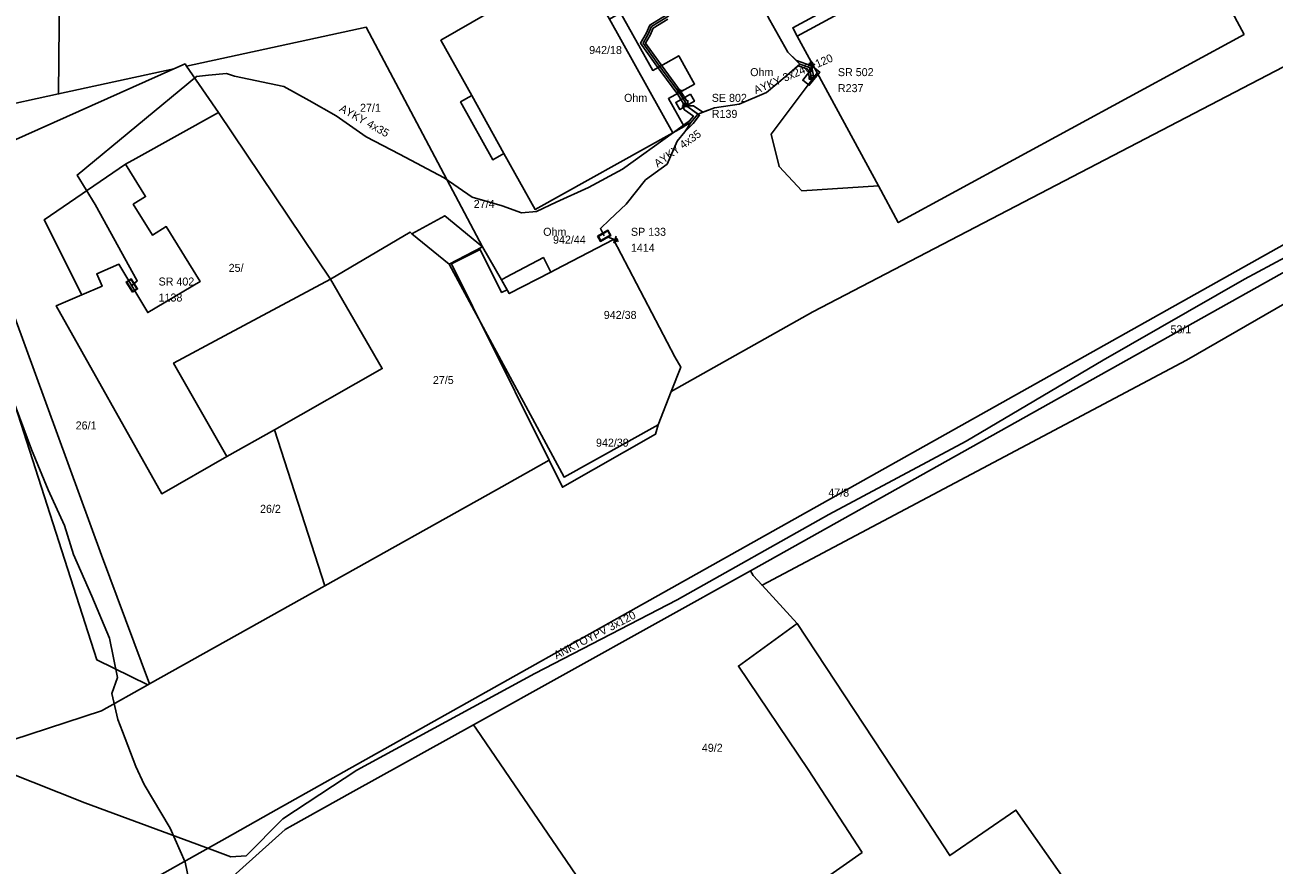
# Model space of a CAD drawing. Extents: x -793400 to -756198, y -1074141 to -1042963.
# Drawn here: x -783184.8 to -783067.8, y -1065311.3 to -1065232.6 of the extents above; entities that cross this region are included whole.
import ezdxf

# ---------------------------------------------------------------- set-up
doc = ezdxf.new("R2010")
doc.units = 0
for name, color, linetype in [('Parcela', 7, 'Continuous'), ('Popiskový text - Parcela', 7, 'Continuous'), ('Popiskový text - Přípojková skříň nn - SJZ', 7, 'Continuous'), ('Popiskový text - Přípojková skříň nn - Typ', 7, 'Continuous'), ('Popiskový text - Rozpojovací skříň nn - SJZ', 7, 'Continuous'), ('Popiskový text - Rozpojovací skříň nn - Typ', 7, 'Continuous'), ('Popiskový text - Uzemnění - Odpor', 7, 'Continuous'), ('Popiskový text - Vedení nn kabelové', 7, 'Continuous'), ('Popiskový text - Vedení vn kabelové', 7, 'Continuous'), ('Skříň', 7, 'Continuous'), ('Spojnice nn', 7, 'Continuous'), ('Spojnice vn', 7, 'Continuous'), ('Stavební objekt', 7, 'Continuous'), ('Uzemnění', 7, 'Continuous'), ('Vedení 22 kV kabelové', 7, 'Continuous'), ('Vedení nn kabelové', 7, 'Continuous')]:
    doc.layers.add(name, color=color, linetype=linetype)

msp = doc.modelspace()

# ---------------------------------------------------------------- linework, layer by layer
at = {"layer": 'Parcela'}
for points in [[(-782802.96, -1065191.56), (-783035.19, -1065351.07), (-783035.53, -1065350.83), (-783038.17, -1065350.24), (-783040.99, -1065346.21), (-783044.07, -1065348.33), (-783047.92, -1065345.19), (-783053.56, -1065344.29), (-783058.74, -1065346.24), (-783070.11, -1065329.81), (-783075.77, -1065329.23), (-783091.97, -1065306.14), (-783098.16, -1065310.4), (-783100.87, -1065306.26), (-783112.47, -1065288.65), (-783115.75, -1065285.08), (-783075.98, -1065264), (-783047.31, -1065247.47), (-783047.3, -1065244.78), (-783016.9, -1065227.41), (-782970.29, -1065201.58), (-782969.82, -1065201.89), (-782969.07, -1065202.37), (-782882.22, -1065152.82)], [(-783169.31, -1065352.34), (-783175.94, -1065340.1), (-783182.62, -1065330.47), (-783184.48, -1065327.78), (-783187.81, -1065328.54), (-783187.72, -1065300.11), (-783177.68, -1065296.84), (-783173.32, -1065294.4), (-783173.16, -1065294.31), (-783156.73, -1065285.12), (-783140.65, -1065276.14), (-783135.72, -1065273.37), (-783134.47, -1065275.89), (-783125.74, -1065270.93), (-783125.51, -1065270.04), (-783124.29, -1065266.93), (-783111, -1065259.46), (-783050.92, -1065228.15), (-783004.72, -1065202.26), (-782983.18, -1065192.04), (-782974.5, -1065189.1), (-782967.33, -1065186.68)], [(-783181.56, -1065226.08), (-783181.69, -1065239.04), (-783194.28, -1065241.77), (-783196.65, -1065233.93), (-783199.83, -1065235.73), (-783237.43, -1065216.95)], [(-783050.92, -1065228.15), (-783111, -1065259.46), (-783124.29, -1065266.93), (-783123.38, -1065264.63), (-783123.94, -1065263.66), (-783129.68, -1065252.69), (-783135.14, -1065255.52), (-783135.55, -1065255.73), (-783136.25, -1065254.38), (-783139.73, -1065256.22), (-783140.19, -1065256.46), (-783141.97, -1065253.35), (-783152.85, -1065232.79), (-783169.7, -1065236.44), (-783169.84, -1065236.23), (-783170.9, -1065236.7), (-783181.69, -1065239.04), (-783181.56, -1065226.08)], [(-783030.13, -1065225.97), (-783047.29, -1065238.34), (-783047.3, -1065242.19), (-783117.31, -1065281.44), (-783154.96, -1065302.57), (-783161.79, -1065306.4), (-783165.39, -1065308.42), (-783174.79, -1065313.7), (-783175.5, -1065314.93), (-783176.75, -1065317.97), (-783176.79, -1065320.46), (-783175.95, -1065323.2), (-783173.92, -1065326.44), (-783170.91, -1065331.24), (-783170.98, -1065331.8), (-783171.31, -1065334.39), (-783166.81, -1065343.66), (-783166.32, -1065344.67), (-783164.64, -1065348.16), (-783161.08, -1065352.99)]]:
    msp.add_lwpolyline(points, dxfattribs=at)
for points in [[(-783237.43, -1065216.95), (-783199.83, -1065235.73), (-783196.65, -1065233.93), (-783194.28, -1065241.77), (-783178.12, -1065292.05), (-783173.32, -1065294.4), (-783177.68, -1065296.84), (-783187.72, -1065300.11), (-783190.56, -1065290.52), (-783205.72, -1065239.34), (-783207.03, -1065237.99), (-783208.59, -1065236.96), (-783235.05, -1065225.06), (-783238.13, -1065225.57), (-783243.03, -1065216.54), (-783256.12, -1065192.4), (-783266.62, -1065172.96), (-783272.44, -1065162), (-783267.78, -1065160.5), (-783264.5, -1065166.6)], [(-783070.56, -1065233.47), (-783079.93, -1065216.01), (-783080.35, -1065215.23), (-783112.88, -1065232.84), (-783112.46, -1065233.62), (-783110.6, -1065237.06), (-783114.9, -1065242.82), (-783114.17, -1065245.85), (-783112.04, -1065248.11), (-783104.86, -1065247.66), (-783103, -1065251.1)], [(-783070.56, -1065233.47), (-783103, -1065251.1), (-783104.86, -1065247.66), (-783112.04, -1065248.11), (-783114.17, -1065245.85), (-783114.9, -1065242.82), (-783110.6, -1065237.06), (-783112.46, -1065233.62), (-783112.88, -1065232.84), (-783080.35, -1065215.23), (-783079.93, -1065216.01)], [(-783133.08, -1065226.62), (-783145.87, -1065234.01), (-783142.97, -1065239.2), (-783144.02, -1065239.79), (-783141, -1065245.2), (-783139.95, -1065244.61), (-783137.01, -1065249.88), (-783124.11, -1065242.68), (-783123.06, -1065242.09), (-783124.53, -1065239.48), (-783122.08, -1065238.11), (-783123.56, -1065235.46), (-783126, -1065236.83), (-783129.01, -1065231.44), (-783130.06, -1065232.03)], [(-783133.08, -1065226.62), (-783130.06, -1065232.03), (-783129.01, -1065231.44), (-783126, -1065236.83), (-783123.56, -1065235.46), (-783122.08, -1065238.11), (-783124.53, -1065239.48), (-783123.06, -1065242.09), (-783124.11, -1065242.68), (-783137.01, -1065249.88), (-783139.95, -1065244.61), (-783141, -1065245.2), (-783144.02, -1065239.79), (-783142.97, -1065239.2), (-783145.87, -1065234.01)], [(-783152.85, -1065232.79), (-783141.97, -1065253.35), (-783145.48, -1065250.45), (-783148.59, -1065252.14), (-783148.74, -1065251.98), (-783156.21, -1065256.38), (-783166.69, -1065240.77), (-783169.7, -1065236.44)], [(-783173.16, -1065294.31), (-783173.32, -1065294.4), (-783178.12, -1065292.05), (-783194.28, -1065241.77), (-783181.69, -1065239.04), (-783170.9, -1065236.7), (-783179.76, -1065240.65), (-783191.05, -1065245.69), (-783177.67, -1065282.27)], [(-783181.91, -1065258.89), (-783172.02, -1065276.5), (-783165.93, -1065273.01), (-783161.45, -1065270.5), (-783156.73, -1065285.12), (-783173.16, -1065294.31), (-783177.67, -1065282.27), (-783191.05, -1065245.69), (-783179.76, -1065240.65), (-783170.9, -1065236.7), (-783169.84, -1065236.23), (-783169.7, -1065236.44), (-783166.69, -1065240.77), (-783174.44, -1065245.09), (-783175.41, -1065245.63), (-783183.05, -1065250.84), (-783179.51, -1065257.86)], [(-783165.93, -1065273.01), (-783172.02, -1065276.5), (-783181.91, -1065258.89), (-783179.51, -1065257.86), (-783183.05, -1065250.84), (-783175.41, -1065245.63), (-783174.44, -1065245.09), (-783166.69, -1065240.77), (-783156.21, -1065256.38), (-783151.35, -1065264.77), (-783161.45, -1065270.5)], [(-783172.94, -1065321.3), (-783175.95, -1065323.2), (-783176.79, -1065320.46), (-783176.75, -1065317.97), (-783175.5, -1065314.93), (-783174.79, -1065313.7), (-783165.39, -1065308.42), (-783161.79, -1065306.4), (-783154.96, -1065302.57), (-783117.31, -1065281.44), (-783047.3, -1065242.19), (-783047.3, -1065244.78), (-783049.56, -1065246.07), (-783116.83, -1065283.73), (-783142.8, -1065298.14), (-783154.07, -1065304.4), (-783160.02, -1065307.71), (-783160.46, -1065307.95), (-783165.63, -1065312.63), (-783167.76, -1065315.47), (-783169.32, -1065319.01)], [(-783075.98, -1065264), (-783115.75, -1065285.08), (-783116.58, -1065284.17), (-783116.83, -1065283.73), (-783049.56, -1065246.07), (-783047.3, -1065244.78), (-783047.31, -1065247.47)], [(-783141.97, -1065253.35), (-783145.08, -1065254.98), (-783148.59, -1065252.14), (-783145.48, -1065250.45)], [(-783140.65, -1065276.14), (-783156.73, -1065285.12), (-783161.45, -1065270.5), (-783151.35, -1065264.77), (-783156.21, -1065256.38), (-783148.74, -1065251.98), (-783148.59, -1065252.14), (-783145.08, -1065254.98), (-783142.12, -1065260.48), (-783135.72, -1065273.37)], [(-783129.68, -1065252.69), (-783123.94, -1065263.66), (-783123.38, -1065264.63), (-783124.29, -1065266.93), (-783125.51, -1065270.04), (-783134.32, -1065274.94), (-783142.12, -1065260.48), (-783145.08, -1065254.98), (-783141.97, -1065253.35), (-783140.19, -1065256.46), (-783139.45, -1065257.75), (-783135.55, -1065255.73), (-783135.14, -1065255.52)], [(-783135.55, -1065255.73), (-783139.45, -1065257.75), (-783140.19, -1065256.46), (-783139.73, -1065256.22), (-783136.25, -1065254.38)], [(-783142.12, -1065260.48), (-783134.32, -1065274.94), (-783125.51, -1065270.04), (-783125.74, -1065270.93), (-783134.47, -1065275.89), (-783135.72, -1065273.37)], [(-783106.38, -1065310.12), (-783125.54, -1065323.56), (-783130.96, -1065315.49), (-783142.51, -1065298.56), (-783142.8, -1065298.14), (-783116.83, -1065283.73), (-783116.58, -1065284.17), (-783115.75, -1065285.08), (-783112.47, -1065288.65), (-783117.97, -1065292.65), (-783111.44, -1065302.35)], [(-783140.59, -1065333.35), (-783153.27, -1065341.6), (-783155.97, -1065337.66), (-783156.77, -1065336.48), (-783169.32, -1065319.01), (-783167.76, -1065315.47), (-783165.63, -1065312.63), (-783160.46, -1065307.95), (-783160.02, -1065307.71), (-783154.07, -1065304.4), (-783142.8, -1065298.14), (-783142.51, -1065298.56), (-783130.96, -1065315.49), (-783125.54, -1065323.56), (-783132.44, -1065328.04)]]:
    msp.add_lwpolyline(points, close=True, dxfattribs=at)
at = {"layer": 'Skříň'}
for points in [[(-783110.97, -1065236.51), (-783111.95, -1065237.75), (-783111.33, -1065238.23), (-783110.35, -1065236.99)], [(-783122.48, -1065239.05), (-783123.85, -1065239.83), (-783123.46, -1065240.51), (-783122.09, -1065239.73)], [(-783131.18, -1065252.37), (-783130.2, -1065251.81), (-783129.92, -1065252.29), (-783130.9, -1065252.86)], [(-783130.22, -1065251.88), (-783131.1, -1065252.39), (-783130.88, -1065252.78), (-783130, -1065252.27)], [(-783174.75, -1065257.62), (-783175.36, -1065256.67), (-783174.89, -1065256.36), (-783174.28, -1065257.31)], [(-783175.28, -1065256.68), (-783174.74, -1065257.54), (-783174.36, -1065257.3), (-783174.9, -1065256.44)]]:
    msp.add_lwpolyline(points, close=True, dxfattribs=at)
at = {"layer": 'Spojnice nn'}
msp.add_line((-783122.39, -1065241.69), (-783121.77, -1065240.93), dxfattribs=at)
for points in [[(-783122.97, -1065239.78), (-783123.5, -1065238.98), (-783125.61, -1065236.09), (-783126.91, -1065234.28), (-783126.43, -1065233.45), (-783126.11, -1065232.73), (-783124.69, -1065231.86), (-783123.47, -1065230.89), (-783122.28, -1065229.8), (-783119.87, -1065228.65), (-783118.22, -1065225.76), (-783117.53, -1065224.72), (-783117.75, -1065223.16), (-783117.5, -1065221.69), (-783117.18, -1065219.94), (-783116.13, -1065219.01), (-783114.57, -1065217.27), (-783112.34, -1065215.9), (-783109.7, -1065214.44), (-783107.04, -1065212.85), (-783105.78, -1065211.66), (-783105.91, -1065210.83), (-783105.63, -1065209.85)], [(-783112.21, -1065236.25), (-783113.33, -1065235.12), (-783115.02, -1065232.13), (-783116.48, -1065229.44), (-783117.09, -1065227.82), (-783117.16, -1065226.43), (-783116.63, -1065225.17), (-783114.88, -1065223.58), (-783111.65, -1065221.59), (-783108.32, -1065220.6), (-783106.59, -1065219.89), (-783103.25, -1065218.43), (-783102.07, -1065217.71), (-783101.76, -1065217.45), (-783101.79, -1065216.92), (-783102.92, -1065215.45), (-783103.77, -1065213.77), (-783104.81, -1065211.73), (-783105.49, -1065210.57), (-783105.63, -1065209.85)], [(-783168.75, -1065237.4), (-783167.65, -1065237.28), (-783165.96, -1065237.13), (-783165.19, -1065237.38), (-783160.59, -1065238.35), (-783158.2, -1065239.66), (-783155.66, -1065241.08), (-783152.86, -1065243.06), (-783149.74, -1065244.67), (-783145.55, -1065246.89), (-783142.94, -1065248.71), (-783140.11, -1065249.52), (-783138.31, -1065250.17), (-783136.9, -1065250.06), (-783135.06, -1065249.18), (-783132.01, -1065247.81), (-783128.85, -1065246.09), (-783124.06, -1065242.65), (-783122.39, -1065241.69)], [(-783112.21, -1065236.25), (-783113.39, -1065237.28), (-783115.34, -1065238.91), (-783117.91, -1065240.01), (-783120.2, -1065240.33), (-783121.77, -1065240.93)], [(-783112.21, -1065236.25), (-783111.3, -1065236.57), (-783111.15, -1065237.37)], [(-783174.82, -1065256.99), (-783174.31, -1065256.56), (-783178.25, -1065249.4), (-783179.96, -1065246.64), (-783168.75, -1065237.4)], [(-783121.77, -1065240.93), (-783122.73, -1065240.26), (-783122.97, -1065239.78)], [(-783122.39, -1065241.69), (-783123, -1065242.6), (-783123.71, -1065243.47), (-783124.64, -1065245.61), (-783126.68, -1065247.09), (-783128.48, -1065249.38), (-783130.06, -1065250.85), (-783130.9, -1065251.66), (-783130.55, -1065252.33)], [(-783186.06, -1065267.4), (-783184.24, -1065272.34), (-783182.68, -1065276.12), (-783181.13, -1065279.49), (-783180.29, -1065282.2), (-783178.56, -1065286.1), (-783176.92, -1065290.04), (-783176.18, -1065293.72), (-783176.69, -1065295.22), (-783176.13, -1065297.65), (-783175.7, -1065298.78), (-783174.46, -1065302.07), (-783173.67, -1065303.75), (-783171.22, -1065307.85), (-783169.84, -1065311.02), (-783169.31, -1065313.58), (-783170.08, -1065316.81), (-783170.38, -1065319.1)]]:
    msp.add_lwpolyline(points, dxfattribs=at)
at = {"layer": 'Spojnice vn'}
msp.add_lwpolyline([(-783217.44, -1065232.14), (-783209.16, -1065235.91), (-783203.96, -1065238.4), (-783200.42, -1065250.14), (-783198.63, -1065261.03), (-783195.48, -1065271.38), (-783191.96, -1065283.45), (-783188.85, -1065293.14), (-783187.71, -1065296.56), (-783186.53, -1065302.56), (-783179.23, -1065305.47), (-783167.3, -1065309.87), (-783165.55, -1065310.52), (-783164.11, -1065310.42), (-783160.68, -1065306.97), (-783153.73, -1065302.41), (-783137.04, -1065293.34), (-783123.72, -1065286.43), (-783109.5, -1065278.44), (-783096.64, -1065271.58), (-783083.79, -1065263.97), (-783070.55, -1065256.39), (-783062.85, -1065252.28)], dxfattribs=at)
at = {"layer": 'Stavební objekt'}
for points in [[(-783070.56, -1065233.47), (-783103, -1065251.1), (-783104.86, -1065247.66), (-783110.6, -1065237.06), (-783112.46, -1065233.62), (-783079.93, -1065216.01)], [(-783124.11, -1065242.68), (-783137.01, -1065249.88), (-783139.95, -1065244.61), (-783142.97, -1065239.2), (-783145.87, -1065234.01), (-783133.08, -1065226.62), (-783130.06, -1065232.03)], [(-783166.69, -1065240.77), (-783156.21, -1065256.38), (-783166.14, -1065261.7), (-783170.91, -1065264.26), (-783165.93, -1065273.01), (-783172.02, -1065276.5), (-783181.91, -1065258.89), (-783179.51, -1065257.86), (-783177.62, -1065257.06), (-783178.12, -1065255.88), (-783176.04, -1065255), (-783173.33, -1065259.53), (-783168.42, -1065256.6), (-783171.6, -1065251.46), (-783172.89, -1065252.26), (-783174.69, -1065249.37), (-783173.53, -1065248.65), (-783175.41, -1065245.63), (-783174.44, -1065245.09)], [(-783129.68, -1065252.69), (-783123.94, -1065263.66), (-783123.38, -1065264.63), (-783124.29, -1065266.93), (-783125.51, -1065270.04), (-783134.32, -1065274.94), (-783142.12, -1065260.48), (-783145.08, -1065254.98), (-783141.97, -1065253.35), (-783140.19, -1065256.46), (-783139.45, -1065257.75), (-783135.55, -1065255.73), (-783135.14, -1065255.52)], [(-783141.97, -1065253.35), (-783140.19, -1065256.46), (-783139.65, -1065257.4), (-783140.17, -1065257.64), (-783142.17, -1065253.61), (-783144.86, -1065254.95), (-783142.86, -1065258.98), (-783142.12, -1065260.48), (-783145.08, -1065254.98)]]:
    msp.add_lwpolyline(points, close=True, dxfattribs=at)
at = {"layer": 'Uzemnění'}
for p, q in [((-783111.1, -1065235.99), (-783111.2, -1065235.99)), ((-783110.8, -1065236.29), (-783111.5, -1065236.29)), ((-783110.93, -1065236.2), (-783111.37, -1065236.2)), ((-783111.01, -1065236.1), (-783111.29, -1065236.1)), ((-783111.15, -1065236.98), (-783111.15, -1065236.29)), ((-783123.21, -1065238.67), (-783123.81, -1065239.01)), ((-783123.36, -1065238.65), (-783123.74, -1065238.87)), ((-783123.47, -1065238.61), (-783123.72, -1065238.75)), ((-783123.61, -1065238.56), (-783123.7, -1065238.61)), ((-783123.17, -1065239.44), (-783123.51, -1065238.84)), ((-783129.65, -1065253.02), (-783129.42, -1065252.37)), ((-783130.18, -1065252.46), (-783129.54, -1065252.7)), ((-783129.53, -1065252.94), (-783129.37, -1065252.52)), ((-783129.41, -1065252.9), (-783129.31, -1065252.63)), ((-783129.27, -1065252.85), (-783129.24, -1065252.76))]:
    msp.add_line(p, q, dxfattribs=at)
at = {"layer": 'Vedení 22 kV kabelové'}
msp.add_lwpolyline([(-783217.44, -1065232.14), (-783209.16, -1065235.91), (-783203.96, -1065238.4), (-783200.42, -1065250.14), (-783198.63, -1065261.03), (-783195.48, -1065271.38), (-783191.96, -1065283.45), (-783188.85, -1065293.14), (-783187.71, -1065296.56), (-783186.53, -1065302.56), (-783179.23, -1065305.47), (-783167.3, -1065309.87), (-783165.55, -1065310.52), (-783164.11, -1065310.42), (-783160.68, -1065306.97), (-783153.73, -1065302.41), (-783137.04, -1065293.34), (-783123.72, -1065286.43), (-783109.5, -1065278.44), (-783096.64, -1065271.58), (-783083.79, -1065263.97), (-783070.55, -1065256.39), (-783062.85, -1065252.28)], dxfattribs=at)
at = {"layer": 'Vedení nn kabelové'}
for points in [[(-783122.86, -1065239.96), (-783122.86, -1065240.12), (-783123.14, -1065240.12), (-783123.14, -1065239.89), (-783123.66, -1065239.09), (-783125.77, -1065236.21), (-783127.15, -1065234.29), (-783126.61, -1065233.36), (-783126.27, -1065232.59), (-783124.8, -1065231.7)], [(-783124.58, -1065232.02), (-783125.95, -1065232.87), (-783126.25, -1065233.54), (-783126.67, -1065234.27), (-783125.45, -1065235.97), (-783123.34, -1065238.87), (-783122.8, -1065239.67), (-783122.7, -1065239.67), (-783122.7, -1065240.09), (-783122.88, -1065240.09), (-783122.88, -1065239.96)], [(-783115.02, -1065232.13), (-783113.33, -1065235.12), (-783112.53, -1065235.92), (-783111.12, -1065236.42), (-783110.95, -1065237.33), (-783111.19, -1065237.33), (-783111.19, -1065237.61), (-783111.03, -1065237.61), (-783111.03, -1065237.46)], [(-783122.83, -1065239.96), (-783122.83, -1065240.18), (-783123.22, -1065240.18), (-783123.04, -1065240.53), (-783122.19, -1065241.13), (-783122.55, -1065241.56), (-783124.06, -1065242.65), (-783128.85, -1065246.09), (-783132.01, -1065247.81), (-783135.06, -1065249.18), (-783136.9, -1065250.06), (-783138.31, -1065250.17), (-783140.11, -1065249.52), (-783142.94, -1065248.71), (-783145.55, -1065246.89), (-783149.74, -1065244.67), (-783152.86, -1065243.06), (-783155.66, -1065241.08), (-783158.2, -1065239.66), (-783160.59, -1065238.35), (-783165.19, -1065237.38), (-783165.96, -1065237.13), (-783167.65, -1065237.28), (-783168.75, -1065237.4), (-783179.96, -1065246.64), (-783178.25, -1065249.4), (-783174.31, -1065256.56), (-783174.46, -1065256.69), (-783174.82, -1065256.99)], [(-783122.91, -1065239.96), (-783122.91, -1065240.15), (-783122.18, -1065240.15), (-783121.32, -1065240.76), (-783120.2, -1065240.33), (-783117.91, -1065240.01), (-783115.34, -1065238.91), (-783113.39, -1065237.28), (-783112.38, -1065236.4), (-783111.48, -1065236.72), (-783111.35, -1065237.41), (-783111.35, -1065237.65), (-783111.01, -1065237.65), (-783111.01, -1065237.46)], [(-783130.55, -1065252.33), (-783130.9, -1065251.66), (-783130.06, -1065250.85), (-783128.48, -1065249.38), (-783126.68, -1065247.09), (-783124.64, -1065245.61), (-783123.71, -1065243.47), (-783123, -1065242.6), (-783122.23, -1065241.82), (-783121.61, -1065241.04), (-783122.73, -1065240.26), (-783122.75, -1065240.22), (-783123, -1065240.22), (-783123, -1065239.89), (-783122.91, -1065239.89), (-783122.91, -1065239.87)], [(-783170.38, -1065319.1), (-783170.08, -1065316.81), (-783169.31, -1065313.58), (-783169.84, -1065311.02), (-783171.22, -1065307.85), (-783173.67, -1065303.75), (-783174.46, -1065302.07), (-783175.7, -1065298.78), (-783176.13, -1065297.65), (-783176.69, -1065295.22), (-783176.18, -1065293.72), (-783176.92, -1065290.04), (-783178.56, -1065286.1), (-783180.29, -1065282.2), (-783181.13, -1065279.49), (-783182.68, -1065276.12), (-783184.24, -1065272.34), (-783186.06, -1065267.4)]]:
    msp.add_lwpolyline(points, dxfattribs=at)

# ---------------------------------------------------------------- texts
at = {"layer": 'Popiskový text - Parcela'}
for s, p in [('942/18', (-783131.96, -1065235.3)), ('27/1', (-783153.44, -1065240.71)), ('27/4', (-783142.78, -1065249.72)), ('942/44', (-783135.35, -1065253.07)), ('25/', (-783165.75, -1065255.71)), ('942/38', (-783130.59, -1065260.12)), ('53/1', (-783077.48, -1065261.47)), ('27/5', (-783146.61, -1065266.22)), ('26/1', (-783180.09, -1065270.48)), ('942/39', (-783131.32, -1065272.09)), ('47/8', (-783109.55, -1065276.77)), ('26/2', (-783162.81, -1065278.29)), ('49/2', (-783121.4, -1065300.68))]:
    msp.add_text(s, height=0.75, dxfattribs=at).set_placement(p)
at = {"layer": 'Popiskový text - Přípojková skříň nn - SJZ'}
for s, p in [('1414', (-783128.05, -1065253.83)), ('1138', (-783172.32, -1065258.49))]:
    msp.add_text(s, height=0.75, dxfattribs=at).set_placement(p)
at = {"layer": 'Popiskový text - Přípojková skříň nn - Typ'}
for s, p in [('SP 133', (-783128.05, -1065252.33)), ('SR 402', (-783172.32, -1065256.99))]:
    msp.add_text(s, height=0.75, dxfattribs=at).set_placement(p)
at = {"layer": 'Popiskový text - Rozpojovací skříň nn - SJZ'}
for s, p in [('R237', (-783108.65, -1065238.87)), ('R139', (-783120.47, -1065241.28))]:
    msp.add_text(s, height=0.75, dxfattribs=at).set_placement(p)
at = {"layer": 'Popiskový text - Rozpojovací skříň nn - Typ'}
for s, p in [('SR 502', (-783108.65, -1065237.37)), ('SE 802', (-783120.47, -1065239.78))]:
    msp.add_text(s, height=0.75, dxfattribs=at).set_placement(p)
at = {"layer": 'Popiskový text - Uzemnění - Odpor'}
for p in [(-783117.15, -1065237.37), (-783128.97, -1065239.78), (-783136.55, -1065252.33)]:
    msp.add_text(' Ohm', height=0.75, dxfattribs=at).set_placement(p)
at = {"layer": 'Popiskový text - Vedení nn kabelové'}
for s, rotation, p in [('AYKY 3x240+120', 23.1475, (-783116.34, -1065239.07)), ('AYKY 4x35', 330.7685, (-783155.45, -1065240.62)), ('AYKY 4x35', 35.9817, (-783125.54, -1065245.96))]:
    msp.add_text(s, height=0.75, rotation=rotation, dxfattribs=at).set_placement(p)
at = {"layer": 'Popiskový text - Vedení vn kabelové'}
msp.add_text('ANKTOYPV 3x120', height=0.75, rotation=27.4447, dxfattribs=at).set_placement((-783135.03, -1065292.02))

doc.saveas('drawing.dxf')
